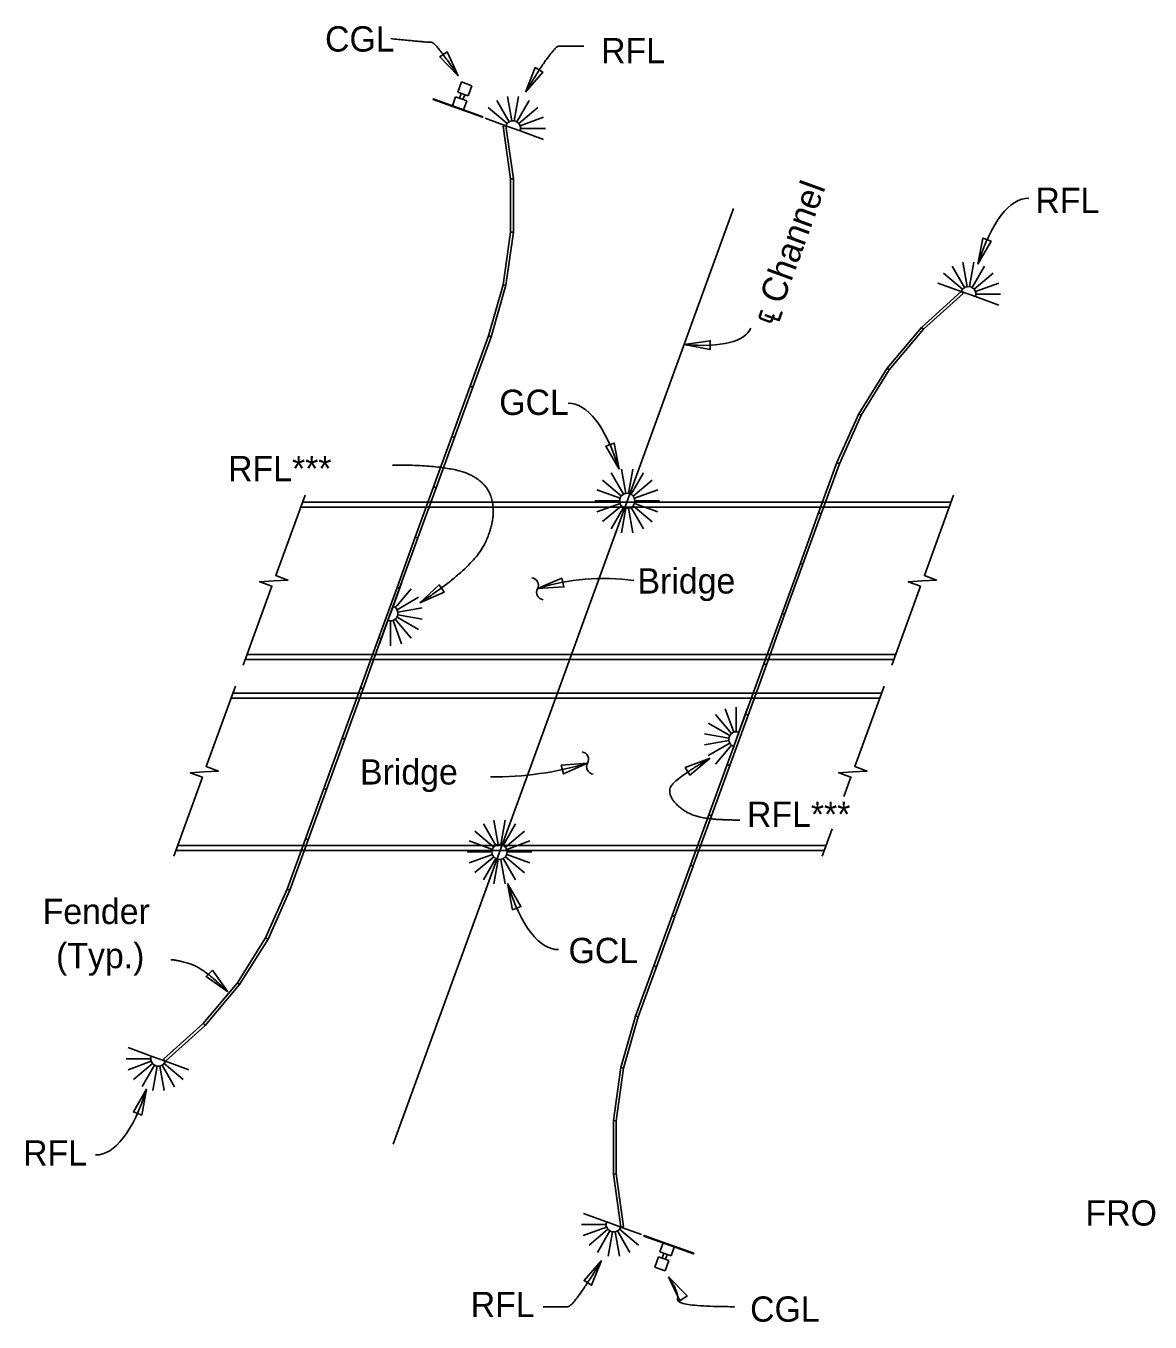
# Model space of a CAD drawing. Extents: x 84082 to 86787, y 72619 to 74101.
# Drawn here: x 84537.8 to 84873.9, y 73695.8 to 74083.2 of the extents above; entities that cross this region are included whole.
import ezdxf

# ---------------------------------------------------------------- set-up
doc = ezdxf.new("R2010")
doc.units = 0
for name, color, linetype in [('Dimension', 7, 'Continuous'), ('Miscellaneous', 7, 'Continuous'), ('NavLight', 7, 'Continuous'), ('SupstrConc', 7, 'Continuous'), ('TextStructures', 7, 'Continuous'), ('Wood', 7, 'Continuous')]:
    doc.layers.add(name, color=color, linetype=linetype)

msp = doc.modelspace()

# ---------------------------------------------------------------- linework, layer by layer
at = {"layer": 'Dimension'}
for points in [[(84667.05, 74068.24), (84663.7, 74075.42), (84661.52, 74073.91)], [(84687.12, 74063.36), (84692.3, 74069.35), (84690.04, 74070.72)], [(84822.41, 74011.94), (84826.34, 74018.82), (84823.86, 74019.73)], [(84734.57, 73987.91), (84742.35, 73986.44), (84742.4, 73989.09)], [(84715.15, 73950.7), (84713.67, 73958.48), (84711.19, 73957.56)], [(84655.58, 73910.72), (84662.84, 73913.9), (84661.39, 73916.11)], [(84690.73, 73914.98), (84698.63, 73915.52), (84698.01, 73918.1)], [(84705.74, 73862.82), (84697.85, 73862.18), (84698.5, 73859.61)], [(84742.34, 73864.32), (84734.93, 73861.52), (84736.26, 73859.24)], [(84681.82, 73826.81), (84683.29, 73819.03), (84685.77, 73819.95)], [(84598.15, 73794.45), (84593.57, 73800.91), (84591.69, 73799.04)], [(84573.88, 73765.44), (84569.95, 73758.57), (84572.44, 73757.66)], [(84709.85, 73714.16), (84704.66, 73708.17), (84706.92, 73706.8)], [(84729.91, 73709.27), (84733.27, 73702.1), (84735.44, 73703.61)]]:
    msp.add_lwpolyline(points, close=True, dxfattribs=at)
for points in [[(84602.77, 73892.15), (84611.35, 73915.71), (84607.71, 73917.04), (84611.93, 73917.3), (84616.15, 73917.56), (84612.5, 73918.89), (84621.25, 73942.91)], [(84796.66, 73892.15), (84805.23, 73915.71), (84801.59, 73917.04), (84805.81, 73917.3), (84810.03, 73917.56), (84806.39, 73918.89), (84815.13, 73942.91)], [(84582, 73835.07), (84590.57, 73858.63), (84586.93, 73859.96), (84591.15, 73860.22), (84595.37, 73860.48), (84591.73, 73861.8), (84600.47, 73885.83)], [(84782.36, 73852.87), (84784.46, 73858.63), (84780.82, 73859.96), (84785.03, 73860.22), (84789.25, 73860.48), (84785.61, 73861.8), (84794.36, 73885.83)], [(84775.88, 73835.07), (84778.83, 73843.18)]]:
    msp.add_lwpolyline(points, dxfattribs=at)
for centre, radius, start, end in [((84688.77, 73916.01), 2.24, 331.7844, 83.5116), ((84710.41, 73852.96), 65.06, 81.9279, 107.6051), ((84692.71, 73913.9), 2.24, 151.7844, 263.5116), ((84703.78, 73863.94), 2.24, 330.7882, 82.5154), ((84677.84, 73956.35), 97.6, 269.3542, 286.6089), ((84707.68, 73861.76), 2.24, 150.7882, 262.5154)]:
    msp.add_arc(centre, radius, start, end, dxfattribs=at)
for centre, major_axis, ratio, start_param, end_param in [((84836.75, 73974.4), (-0.91, -57.27), 0.343516, 3.141594, 4.002916), ((84689.49, 74018.93), (-65, 26.05), 0.265294, 2.43766, 3.141592), ((84700.81, 73913.16), (0.91, -57.27), 0.343516, 2.28027, 3.141592), ((84696.15, 73864.36), (-0.91, 57.27), 0.343516, 2.28027, 3.141592), ((84559.54, 73802.99), (0.91, 57.27), 0.343516, 3.141594, 4.002916)]:
    msp.add_ellipse(centre, major_axis=major_axis, ratio=ratio, start_param=start_param, end_param=end_param, dxfattribs=at)
for points in [[(84667.05, 74068.24), (84660.22, 74078.32), (84657.86, 74078.23), (84646.87, 74079.37)], [(84704.56, 74077.14), (84698.8, 74077.14), (84695.49, 74077.14), (84687.12, 74063.36)], [(84647.44, 73951.93), (84663.85, 73951.93), (84676.01, 73946.71), (84678.44, 73935.64), (84671.51, 73921.18), (84655.58, 73910.72)], [(84751.23, 73845.82), (84742.86, 73845.82), (84735.19, 73847.74), (84729.86, 73852.89), (84730.82, 73857.6), (84742.34, 73864.32)], [(84581.13, 73804.06), (84583.15, 73804.06), (84591.17, 73801.44), (84598.15, 73794.45)], [(84692.4, 73700.38), (84698.16, 73700.38), (84701.47, 73700.38), (84709.85, 73714.16)], [(84729.91, 73709.27), (84733.05, 73704.74), (84732.18, 73700.38), (84749.62, 73700.38)]]:
    msp.add_open_spline(points, degree=2, dxfattribs=at)
at = {"layer": 'Miscellaneous'}
for p, q in [((84698.48, 73888.76), (84749.36, 74028.56)), ((84647.6, 73748.96), (84698.48, 73888.76))]:
    msp.add_line(p, q, dxfattribs=at)
at = {"layer": 'NavLight'}
for p, q in [((84668.01, 74066.41), (84666.91, 74063.34)), ((84670, 74062.23), (84666.91, 74063.34)), ((84671.1, 74065.3), (84668.01, 74066.41)), ((84671.1, 74065.3), (84670, 74062.23)), ((84665.31, 74059.3), (84666.26, 74061.95)), ((84669.61, 74060.75), (84666.26, 74061.95)), ((84667.41, 74061.54), (84667.92, 74062.98)), ((84668.47, 74061.16), (84668.98, 74062.6)), ((84668.66, 74058.1), (84669.61, 74060.75)), ((84682.3, 74054.51), (84678.59, 74060.92)), ((84683.03, 74054.78), (84681.74, 74062.07)), ((84683.81, 74054.78), (84685.1, 74062.07)), ((84684.55, 74054.51), (84688.25, 74060.92)), ((84681.31, 74053.33), (84675.13, 74055.58)), ((84681.7, 74054.01), (84676.03, 74058.77)), ((84685.14, 74054.01), (84690.81, 74058.77)), ((84685.57, 74053.33), (84692.53, 74055.86)), ((84685.53, 74051.78), (84681.31, 74053.33)), ((84685.56, 74051.77), (84692.52, 74049.23)), ((84685.7, 74052.55), (84693.1, 74052.55)), ((84817.78, 74004.47), (84812.11, 74009.23)), ((84818.38, 74004.99), (84814.68, 74011.4)), ((84819.15, 74005.24), (84817.86, 74012.52)), ((84819.93, 74005.24), (84821.21, 74012.52)), ((84820.66, 74004.97), (84824.36, 74011.38)), ((84821.26, 74004.47), (84826.93, 74009.22)), ((84817.39, 74003.79), (84810.43, 74006.32)), ((84821.65, 74003.79), (84828.61, 74006.32)), ((84817.42, 74003.77), (84821.65, 74002.25)), ((84821.65, 74002.25), (84828.61, 73999.72)), ((84821.79, 74003.02), (84829.19, 74003.02)), ((84717.18, 73943.43), (84715.9, 73950.72)), ((84717.97, 73943.43), (84719.25, 73950.72)), ((84715.85, 73942.66), (84710.18, 73947.42)), ((84716.45, 73943.17), (84712.75, 73949.58)), ((84718.7, 73943.17), (84722.4, 73949.58)), ((84719.33, 73942.67), (84725, 73947.43)), ((84715.46, 73941.99), (84708.5, 73944.52)), ((84719.72, 73941.98), (84726.68, 73944.51)), ((84715.32, 73941.22), (84707.92, 73941.22)), ((84715.46, 73940.45), (84708.5, 73937.92)), ((84715.85, 73939.77), (84710.18, 73935.01)), ((84716.45, 73939.27), (84712.75, 73932.86)), ((84718.7, 73939.27), (84722.4, 73932.86)), ((84719.33, 73939.76), (84725, 73935)), ((84719.72, 73940.45), (84726.68, 73937.92)), ((84719.86, 73941.23), (84727.26, 73941.23)), ((84717.18, 73939), (84715.9, 73931.71)), ((84717.97, 73939), (84719.25, 73931.71)), ((84647.57, 73909.68), (84650.1, 73916.64)), ((84648.24, 73909.29), (84653, 73914.96)), ((84648.75, 73908.69), (84655.16, 73912.4)), ((84646.01, 73905.46), (84647.57, 73909.68)), ((84649.01, 73907.96), (84656.3, 73909.25)), ((84646, 73905.43), (84643.47, 73898.47)), ((84646.78, 73905.29), (84646.78, 73897.89)), ((84647.56, 73905.42), (84650.1, 73898.46)), ((84648.24, 73905.85), (84653, 73900.18)), ((84648.75, 73906.44), (84655.16, 73902.74)), ((84649.01, 73907.18), (84656.3, 73905.89)), ((84748.72, 73871.67), (84743.96, 73877.34)), ((84749.39, 73872.06), (84746.86, 73879.02)), ((84750.16, 73872.2), (84750.16, 73879.6)), ((84750.93, 73872.06), (84753.47, 73879.02)), ((84748.22, 73871.07), (84741.8, 73874.77)), ((84747.95, 73870.34), (84740.66, 73871.62)), ((84747.95, 73869.56), (84740.66, 73868.27)), ((84749.41, 73867.83), (84750.93, 73872.06)), ((84748.2, 73868.79), (84741.78, 73865.09)), ((84748.71, 73868.19), (84743.95, 73862.52)), ((84749.4, 73867.8), (84746.87, 73860.84)), ((84677.66, 73837.75), (84671.99, 73842.5)), ((84678.26, 73838.25), (84674.56, 73844.66)), ((84679, 73838.52), (84677.71, 73845.81)), ((84679.78, 73838.52), (84681.06, 73845.81)), ((84680.51, 73838.25), (84684.21, 73844.66)), ((84681.15, 73837.76), (84686.82, 73842.51)), ((84677.27, 73837.07), (84670.32, 73839.6)), ((84681.54, 73837.07), (84688.49, 73839.6)), ((84677.14, 73836.3), (84669.74, 73836.3)), ((84677.27, 73835.53), (84670.32, 73833)), ((84677.66, 73834.85), (84671.99, 73830.1)), ((84681.15, 73834.85), (84686.82, 73830.09)), ((84681.54, 73835.53), (84688.49, 73833)), ((84681.67, 73836.32), (84689.07, 73836.32)), ((84678.26, 73834.35), (84674.56, 73827.94)), ((84679, 73834.08), (84677.71, 73826.79)), ((84679.78, 73834.08), (84681.06, 73826.79)), ((84680.51, 73834.35), (84684.21, 73827.94)), ((84575.31, 73775.27), (84568.35, 73777.8)), ((84575.17, 73774.5), (84567.77, 73774.5)), ((84575.31, 73773.73), (84568.35, 73771.2)), ((84575.7, 73773.05), (84570.03, 73768.29)), ((84576.3, 73772.55), (84572.6, 73766.14)), ((84579.54, 73773.74), (84575.31, 73775.27)), ((84578.58, 73772.53), (84582.28, 73766.12)), ((84579.18, 73773.04), (84584.85, 73768.28)), ((84579.57, 73773.73), (84586.53, 73771.2)), ((84577.03, 73772.28), (84575.75, 73764.99)), ((84577.81, 73772.28), (84579.1, 73764.99)), ((84711.4, 73725.75), (84704.45, 73728.28)), ((84711.26, 73724.97), (84703.86, 73724.97)), ((84711.39, 73724.19), (84704.44, 73721.66)), ((84711.82, 73723.51), (84706.15, 73718.75)), ((84712.42, 73723.01), (84708.72, 73716.6)), ((84711.43, 73725.74), (84715.66, 73724.19)), ((84713.15, 73722.74), (84711.87, 73715.45)), ((84713.93, 73722.74), (84715.22, 73715.45)), ((84714.67, 73723.01), (84718.37, 73716.6)), ((84715.27, 73723.51), (84720.94, 73718.75)), ((84715.66, 73724.19), (84721.83, 73721.94)), ((84728.3, 73719.42), (84727.35, 73716.77)), ((84725.86, 73712.22), (84726.96, 73715.28)), ((84726.96, 73715.28), (84730.05, 73714.18)), ((84727.35, 73716.77), (84730.7, 73715.57)), ((84728.5, 73716.36), (84727.98, 73714.92)), ((84729.55, 73715.98), (84729.04, 73714.54)), ((84731.65, 73718.21), (84730.7, 73715.57)), ((84725.86, 73712.22), (84728.95, 73711.11)), ((84728.95, 73711.11), (84730.05, 73714.18))]:
    msp.add_line(p, q, dxfattribs=at)
for centre in [(84717.57, 73941.22), (84679.39, 73836.3)]:
    msp.add_circle(centre, 2.25, dxfattribs=at)
for centre, start, end in [((84683.42, 74052.56), 339.6086, 160), ((84819.54, 74003.02), 340, 160.3914), ((84646.8, 73907.57), 249.6086, 70), ((84750.16, 73869.95), 70, 250.3914), ((84577.42, 73774.5), 160, 340.3914), ((84713.54, 73724.96), 159.6086, 340)]:
    msp.add_arc(centre, 2.25, start, end, dxfattribs=at)
at = {"layer": 'SupstrConc'}
for p, q in [((84619.93, 73939.3), (84813.82, 73939.3)), ((84620.5, 73940.84), (84814.38, 73940.84)), ((84797.24, 73893.76), (84603.36, 73893.76)), ((84797.8, 73895.3), (84603.92, 73895.3)), ((84793.04, 73882.22), (84599.16, 73882.22)), ((84793.6, 73883.76), (84599.72, 73883.76)), ((84776.47, 73836.68), (84582.58, 73836.68)), ((84777.03, 73838.22), (84583.14, 73838.22))]:
    msp.add_line(p, q, dxfattribs=at)
at = {"layer": 'Wood'}
for p, q in [((84681.31, 74053.33), (84680.48, 74053.22)), ((84682.7, 74037.43), (84680.48, 74053.22)), ((84683.53, 74037.49), (84681.31, 74053.33)), ((84682.7, 74037.43), (84683.53, 74037.49)), ((84682.7, 74021.55), (84682.7, 74037.43)), ((84683.53, 74021.49), (84683.53, 74037.49)), ((84680.49, 74005.82), (84682.7, 74021.55)), ((84681.31, 74005.64), (84683.53, 74021.49)), ((84682.7, 74021.55), (84683.53, 74021.49)), ((84676.1, 73990.52), (84680.49, 74005.82)), ((84676.9, 73990.26), (84681.31, 74005.64)), ((84680.49, 74005.82), (84681.31, 74005.64)), ((84805.53, 73993.08), (84817.42, 74003.79)), ((84806.13, 73992.5), (84817.98, 74003.17)), ((84817.42, 74003.79), (84817.98, 74003.17)), ((84670.64, 73975.51), (84676.1, 73990.52)), ((84671.42, 73975.23), (84676.9, 73990.26)), ((84676.1, 73990.52), (84676.9, 73990.26)), ((84795.25, 73980.83), (84805.53, 73993.08)), ((84795.92, 73980.33), (84806.13, 73992.5)), ((84806.13, 73992.5), (84805.53, 73993.08)), ((84786.77, 73967.26), (84795.25, 73980.83)), ((84787.51, 73966.86), (84795.92, 73980.33)), ((84795.92, 73980.33), (84795.25, 73980.83)), ((84665.17, 73960.48), (84670.64, 73975.51)), ((84665.95, 73960.19), (84671.42, 73975.23)), ((84671.42, 73975.23), (84670.64, 73975.51)), ((84780.26, 73952.64), (84786.77, 73967.26)), ((84781.04, 73952.33), (84787.51, 73966.86)), ((84787.51, 73966.86), (84786.77, 73967.26)), ((84659.7, 73945.44), (84665.17, 73960.48)), ((84660.48, 73945.16), (84665.95, 73960.19)), ((84665.95, 73960.19), (84665.17, 73960.48)), ((84774.79, 73937.61), (84780.26, 73952.64)), ((84775.57, 73937.32), (84781.04, 73952.33)), ((84781.04, 73952.33), (84780.26, 73952.64)), ((84654.22, 73930.41), (84659.7, 73945.44)), ((84655.01, 73930.12), (84660.48, 73945.16)), ((84660.48, 73945.16), (84659.7, 73945.44)), ((84769.32, 73922.57), (84774.79, 73937.61)), ((84770.1, 73922.29), (84775.57, 73937.32)), ((84774.79, 73937.61), (84775.57, 73937.32)), ((84654.22, 73930.41), (84648.75, 73915.37)), ((84655.01, 73930.12), (84649.53, 73915.09)), ((84655.01, 73930.12), (84654.22, 73930.41)), ((84763.84, 73907.54), (84769.32, 73922.57)), ((84764.63, 73907.25), (84770.1, 73922.29)), ((84769.32, 73922.57), (84770.1, 73922.29)), ((84643.28, 73900.34), (84648.75, 73915.37)), ((84643.28, 73900.34), (84648.75, 73915.37)), ((84649.53, 73915.09), (84644.06, 73900.05)), ((84649.53, 73915.09), (84644.06, 73900.05)), ((84649.53, 73915.09), (84648.75, 73915.37)), ((84649.53, 73915.09), (84648.75, 73915.37)), ((84758.37, 73892.5), (84763.84, 73907.54)), ((84759.16, 73892.22), (84764.63, 73907.25)), ((84763.84, 73907.54), (84764.63, 73907.25)), ((84643.28, 73900.34), (84637.81, 73885.3)), ((84644.06, 73900.05), (84638.59, 73885.02)), ((84644.06, 73900.05), (84643.28, 73900.34)), ((84758.37, 73892.5), (84752.9, 73877.47)), ((84759.16, 73892.22), (84753.68, 73877.18)), ((84758.37, 73892.5), (84759.16, 73892.22)), ((84637.81, 73885.3), (84632.34, 73870.29)), ((84638.59, 73885.02), (84633.12, 73869.98)), ((84638.59, 73885.02), (84637.81, 73885.3)), ((84752.9, 73877.47), (84747.43, 73862.43)), ((84748.21, 73862.14), (84753.68, 73877.18)), ((84752.9, 73877.47), (84753.68, 73877.18)), ((84632.33, 73870.27), (84626.87, 73855.26)), ((84633.12, 73869.98), (84627.64, 73854.95)), ((84633.12, 73869.98), (84632.33, 73870.27)), ((84747.43, 73862.43), (84741.96, 73847.39)), ((84748.21, 73862.14), (84742.74, 73847.11)), ((84747.43, 73862.43), (84748.21, 73862.14)), ((84626.86, 73855.23), (84621.39, 73840.2)), ((84627.64, 73854.95), (84622.17, 73839.91)), ((84627.64, 73854.95), (84626.86, 73855.23)), ((84741.96, 73847.39), (84736.48, 73832.36)), ((84742.74, 73847.11), (84737.28, 73832.1)), ((84741.96, 73847.39), (84742.74, 73847.11)), ((84621.39, 73840.2), (84615.93, 73825.19)), ((84622.17, 73839.91), (84616.7, 73824.88)), ((84622.17, 73839.91), (84621.39, 73840.2)), ((84736.48, 73832.36), (84731.01, 73817.32)), ((84737.27, 73832.07), (84731.8, 73817.07)), ((84736.48, 73832.36), (84737.27, 73832.07)), ((84615.93, 73825.19), (84609.45, 73810.65)), ((84616.7, 73824.88), (84610.19, 73810.26)), ((84615.93, 73825.19), (84616.7, 73824.88)), ((84731.01, 73817.32), (84725.54, 73802.29)), ((84731.79, 73817.04), (84726.32, 73802)), ((84731.01, 73817.32), (84731.79, 73817.04)), ((84609.45, 73810.65), (84601.04, 73797.18)), ((84610.19, 73810.26), (84601.71, 73796.69)), ((84609.45, 73810.65), (84610.19, 73810.26)), ((84720.07, 73787.25), (84725.54, 73802.29)), ((84726.32, 73802), (84720.86, 73787)), ((84725.54, 73802.29), (84726.32, 73802)), ((84601.04, 73797.18), (84590.83, 73785.01)), ((84601.71, 73796.69), (84591.43, 73784.43)), ((84601.04, 73797.18), (84601.71, 73796.69)), ((84590.83, 73785.01), (84578.98, 73774.35)), ((84591.43, 73784.43), (84579.54, 73773.73)), ((84590.83, 73785.01), (84591.43, 73784.43)), ((84720.07, 73787.25), (84715.66, 73771.87)), ((84720.86, 73787), (84716.47, 73771.7)), ((84720.86, 73787), (84720.07, 73787.25)), ((84579.54, 73773.73), (84578.98, 73774.35)), ((84715.66, 73771.87), (84713.43, 73756.03)), ((84716.47, 73771.7), (84714.26, 73755.97)), ((84716.47, 73771.7), (84715.66, 73771.87)), ((84713.43, 73756.03), (84713.43, 73740.03)), ((84714.26, 73755.97), (84713.43, 73756.03)), ((84714.26, 73755.97), (84714.26, 73740.09)), ((84714.26, 73740.09), (84713.43, 73740.03)), ((84713.43, 73740.03), (84715.66, 73724.19)), ((84714.26, 73740.09), (84716.48, 73724.3)), ((84715.66, 73724.19), (84716.48, 73724.3))]:
    msp.add_line(p, q, dxfattribs=at)
for points in [[(84669.04, 74057.77), (84659.51, 74061.18), (84659.57, 74061.36), (84664.87, 74059.46)], [(84664.87, 74059.46), (84674.4, 74056.04), (84674.34, 74055.87), (84669.04, 74057.77)], [(84732.09, 73718.06), (84722.56, 73721.47), (84722.63, 73721.65), (84727.92, 73719.75)], [(84727.92, 73719.75), (84737.45, 73716.33), (84737.39, 73716.16), (84732.09, 73718.06)]]:
    msp.add_lwpolyline(points, dxfattribs=at)

# ---------------------------------------------------------------- texts
at = {"layer": 'Dimension'}
for s, p in [('Fender', (84542.82, 73814.75)), ('(Typ.)', (84546.84, 73801.55))]:
    msp.add_text(s, height=7.56, dxfattribs=at).set_placement(p)
at = {"layer": 'TextStructures'}
for s, p in [('CGL', (84627.24, 74075.49)), ('RFL', (84709.76, 74072)), ('RFL', (84839.6, 74027.25)), ('GCL', (84679.32, 73966.9)), ('RFL***', (84598.26, 73947.09)), ('Bridge ', (84720.65, 73913.52)), ('Bridge ', (84637.7, 73856.44)), ('RFL***', (84753.37, 73843.76)), ('GCL', (84700.03, 73803.06)), ('RFL', (84536.99, 73742.57)), ('FROM POWER SOURCE', (84854.57, 73724.62)), ('RFL', (84670.78, 73697.26)), ('CGL', (84754.3, 73695.89))]:
    msp.add_text(s, height=7.56, dxfattribs=at).set_placement(p)
msp.add_text('℄ Channel', height=7.56, rotation=70, dxfattribs=at).set_placement((84761.72, 73993.17))

doc.saveas('drawing.dxf')
